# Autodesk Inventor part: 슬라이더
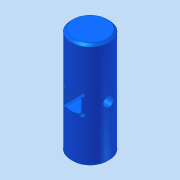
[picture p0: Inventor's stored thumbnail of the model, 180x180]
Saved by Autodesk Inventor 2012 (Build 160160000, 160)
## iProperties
Company: 한국ATC센터
Created: 2015-04
Part Number: 슬라이더
Document SubType Name: Modeling
Designer: KYOUNG IL JANG
Density: 7.85 g/cm^3
Material: 강
Author: KYOUNG IL JANG
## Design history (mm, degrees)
sketch "스케치1"
  geometry: C1 r 9 at (0, 0); 1 further point
  constraints: 1 centre point, 1 coincident
  dimensions: "d0" = 18 diameter of C1
extrude "돌출1" new body sketch "스케치1" stored distance "d1" = 50; taper "d2" = 0 deg
node "작업 평면1"
sketch "스케치3"
  geometry: L1 (4, 25)-(-4, 25); L2 (-4, 25)-(-4, -25); L3 (-4, -25)-(4, -25); L4 (4, -25)-(4, 25); 3 further points
  constraints: 8 end point, 2 midpoint, 2 parallel, 1 horizontal, 1 horizontal alignment, 1 perpendicular, 1 vertical alignment
  dimensions: "d5" = 8 distance of L1.start L1.end; "d6" = 50 distance of L1.end L2.end
extrude "돌출3" cut sketch "스케치3" stored distance "d7" = 8; taper "d8" = 0 deg
sketch "스케치4"
  geometry: 5 further points
hole "구멍1" sketch "스케치4" at (4, 4), (-4, 4), (-4, -4), (4, -4) diameter "d9" = 2; stored, may be unused: countersink angle "d13" = 90 deg, drill point angle "d15" = 118 deg; dims "d10" = 6, "d11" = 4, "d12" = 2, "d14" = 8
node "작업 평면2"
sketch "스케치5"
  geometry: 1 further point
hole "구멍2" sketch "스케치5" at (0, 0) diameter "d16" = 5; stored, may be unused: countersink angle "d20" = 90 deg, drill point angle "d22" = 118 deg; dims "d17" = 6, "d18" = 4, "d19" = 2, "d21" = 8
chamfer "모따기1" distance "d23" = 1; stored, may be unused: second distance "d24" = 2, angle "d25" = 45 deg
node "솔리드1"
mirror "대칭1"
